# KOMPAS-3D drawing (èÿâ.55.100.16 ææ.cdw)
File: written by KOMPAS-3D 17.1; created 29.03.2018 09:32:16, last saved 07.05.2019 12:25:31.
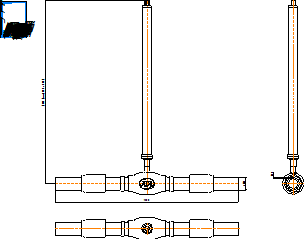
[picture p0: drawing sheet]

Sheet 1: A4, portrait

Title block, sheet 1: name: КШГ.55.100.16 СС; material: Внимание! Данный продукт является объектом авторского права ООО «Торговый Дом АДЛ». / Запрещается изменение, копирование, распространение / (в том числе путем копирования на другие сайты и ресурсы в Интернете) / или любое иное использование информации и объектов без предварительного / согласия правообладателя (ООО «Торговый Дом АДЛ»).; sheets: 1; organisation: ООО "Торговый дом АДЛ"; sheet format: A4; stored path: C:\Users\tra\Desktop\2д чертежи\Шаровые краны БИВАЛ\КШ_Бивал_серия_44_45_55\KOMPAS 2D\КШГ.55.100.16 СС.cdw

Views: Вид 1, Проекционный вид 2
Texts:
  kka
  adl
  (от 425 до 5000)
Dimensions and other numbers on the sheet: 1500; 110; 12,3; 1:1; 1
